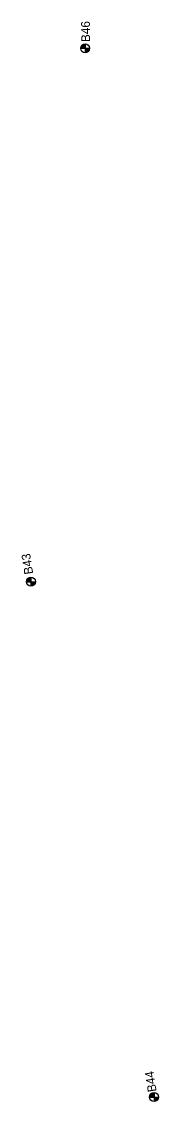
# Model space of a CAD drawing. Extents: x 331323 to 388339, y 121519 to 205315.
# Drawn here: x 360205 to 360361, y 152739 to 153967 of the extents above; entities that cross this region are included whole.
import ezdxf

# ---------------------------------------------------------------- set-up
doc = ezdxf.new("R2010")
doc.units = 0
for name, color, linetype in [('E_SOIL_BORE1 [KAPUR_CADDS_LEVELS]', 7, 'Continuous'), ('E_SOIL_BORE2 [KAPUR_CADDS_LEVELS]', 7, 'Continuous'), ('P_MARK', 7, 'Continuous')]:
    doc.layers.add(name, color=color, linetype=linetype)

msp = doc.modelspace()

# ---------------------------------------------------------------- linework, layer by layer
at = {"layer": 'P_MARK'}
for p, q in [((360277.6, 153941.2), (360277.6, 153931.2)), ((360272.6, 153936.2), (360282.6, 153936.2)), ((360211, 153330), (360221, 153330)), ((360216, 153335), (360216, 153325)), ((360356.1, 152749.3), (360356.1, 152739.3)), ((360351.1, 152744.3), (360361.1, 152744.3))]:
    msp.add_line(p, q, dxfattribs=at)
for centre in [(360277.6, 153936.2), (360216, 153330), (360356.1, 152744.3)]:
    msp.add_circle(centre, 5, dxfattribs=at)
for centre, radius, start, end in [((360277.6, 153936.2), 4.5, 89.9869, 179.9869), ((360277.6, 153936.2), 4, 89.9869, 179.9869), ((360277.6, 153936.2), 3.5, 89.9869, 179.9869), ((360277.6, 153936.2), 3, 89.9869, 179.9869), ((360277.6, 153936.2), 2.5, 89.9869, 179.9869), ((360277.6, 153936.2), 2, 89.9869, 179.9869), ((360277.6, 153936.2), 1.5, 89.9869, 179.9869), ((360277.6, 153936.2), 1, 89.9869, 179.9869), ((360277.6, 153936.2), 0.5, 89.9869, 179.9869), ((360277.6, 153936.2), 4.5, 269.9869, 359.9869), ((360277.6, 153936.2), 4, 269.9869, 359.9869), ((360277.6, 153936.2), 3.5, 269.9869, 359.9869), ((360277.6, 153936.2), 3, 269.9869, 359.9869), ((360277.6, 153936.2), 2.5, 269.9869, 359.9869), ((360277.6, 153936.2), 2, 269.9869, 359.9869), ((360277.6, 153936.2), 1.5, 269.9869, 359.9869), ((360277.6, 153936.2), 1, 269.9869, 359.9869), ((360277.6, 153936.2), 0.5, 269.9869, 359.9869), ((360216, 153330), 4.5, 89.9869, 179.9869), ((360216, 153330), 4, 89.9869, 179.9869), ((360216, 153330), 3.5, 89.9869, 179.9869), ((360216, 153330), 3, 89.9869, 179.9869), ((360216, 153330), 2.5, 89.9869, 179.9869), ((360216, 153330), 2, 89.9869, 179.9869), ((360216, 153330), 1.5, 89.9869, 179.9869), ((360216, 153330), 1, 89.9869, 179.9869), ((360216, 153330), 0.5, 89.9869, 179.9869), ((360216, 153330), 4.5, 269.9869, 359.9869), ((360216, 153330), 4, 269.9869, 359.9869), ((360216, 153330), 3.5, 269.9869, 359.9869), ((360216, 153330), 3, 269.9869, 359.9869), ((360216, 153330), 2.5, 269.9869, 359.9869), ((360216, 153330), 2, 269.9869, 359.9869), ((360216, 153330), 1.5, 269.9869, 359.9869), ((360216, 153330), 1, 269.9869, 359.9869), ((360216, 153330), 0.5, 269.9869, 359.9869), ((360356.1, 152744.3), 4.5, 89.9869, 179.9869), ((360356.1, 152744.3), 4, 89.9869, 179.9869), ((360356.1, 152744.3), 3.5, 89.9869, 179.9869), ((360356.1, 152744.3), 3, 89.9869, 179.9869), ((360356.1, 152744.3), 2.5, 89.9869, 179.9869), ((360356.1, 152744.3), 2, 89.9869, 179.9869), ((360356.1, 152744.3), 1.5, 89.9869, 179.9869), ((360356.1, 152744.3), 1, 89.9869, 179.9869), ((360356.1, 152744.3), 0.5, 89.9869, 179.9869), ((360356.1, 152744.3), 4.5, 269.9869, 359.9869), ((360356.1, 152744.3), 4, 269.9869, 359.9869), ((360356.1, 152744.3), 3.5, 269.9869, 359.9869), ((360356.1, 152744.3), 3, 269.9869, 359.9869), ((360356.1, 152744.3), 2.5, 269.9869, 359.9869), ((360356.1, 152744.3), 2, 269.9869, 359.9869), ((360356.1, 152744.3), 1.5, 269.9869, 359.9869), ((360356.1, 152744.3), 1, 269.9869, 359.9869), ((360356.1, 152744.3), 0.5, 269.9869, 359.9869)]:
    msp.add_arc(centre, radius, start, end, dxfattribs=at)

# ---------------------------------------------------------------- texts
at = {"layer": 'E_SOIL_BORE1 [KAPUR_CADDS_LEVELS]'}
for s, p in [('B43', (360218.6, 153339.1)), ('B44', (360359.1, 152750.8))]:
    msp.add_text(s, height=10, rotation=98.8576, dxfattribs=at).set_placement(p)
at = {"layer": 'E_SOIL_BORE2 [KAPUR_CADDS_LEVELS]'}
msp.add_text('B46', height=10, rotation=90.6368, dxfattribs=at).set_placement((360283.3, 153943.4))

doc.saveas('drawing.dxf')
